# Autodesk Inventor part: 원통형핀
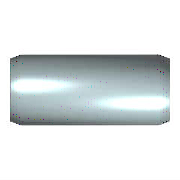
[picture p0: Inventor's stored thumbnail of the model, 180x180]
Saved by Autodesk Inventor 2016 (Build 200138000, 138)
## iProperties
IsCustomPart: 1
Created: 2012-02
Part Number: 원통형핀
Material: 강철, 연강
Description: 평행 핀
Document SubType Name: Modeling
Standard: KS B 1320
Designer: mduedu
Standards Organization: KS
Language: ko-KR
Size Designation: B 2 x  14
Categories: <MemberInstance><Categories><Category DisplayName="조임쇠" InternalName="e4da775c-781d-43d5-af7c-5136215cf5a6" Mnemonic="FSTN"><Category DisplayName="핀" InternalNa
Density: 1 g/cm^3
Appearance: 파란색 - 벽 페인트 - 광택
Author: mduedu
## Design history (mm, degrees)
sketch "스케치"
  geometry: C1 r 1 at (0, 0); 1 further point
  constraints: 1 centre point, 1 coincident
  dimensions: "d1" = 2 diameter of C1 (= NND)
extrude "본체" new body sketch "스케치" distance "d2" = 14 (= NLG); taper "d3" = 0 deg
chamfer "스케치2" distance "d8" = 0.35 (= PHH); stored, may be unused: angle "d9" = 15 deg (= FAWI), second distance "d12" = 0.35 (= PHH)
node "작업 평면1"
body "Solid1"
chamfer "모따기1" distance "d4" = 0.35 (= PHH); stored, may be unused: angle "d5" = 15 deg (= FAWI), second distance "d11" = 0.35 (= PHH)
other parameters: "NND" = 2 [user parameter; used in 1 equation term], "NLG" = 14 [user parameter; used in 1 equation term], "PHH" = 0.35 [user parameter; used in 4 equation terms], "FAWI" = 15 deg [user parameter; used in 2 equation terms], "d13" = 0, "d15" = 0, "d16" = 0, "KAH" = 0.25 [user parameter]
